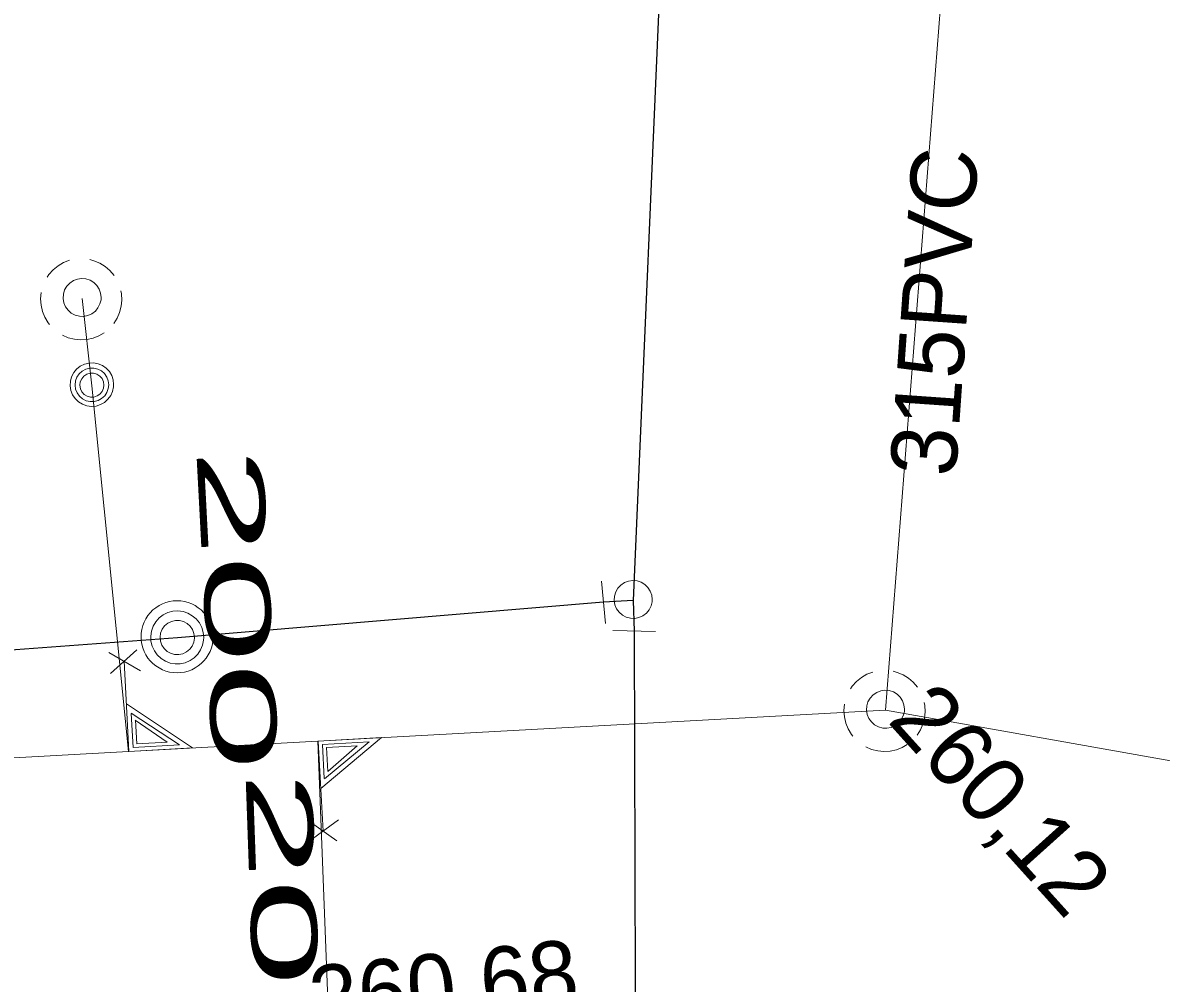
# Model space of a CAD drawing. Extents: x -732074 to -731966, y -1048695 to -1047982.
# Drawn here: x -732046.71 to -732032.89, y -1048041.73 to -1048030.06 of the extents above; entities that cross this region are included whole.
import ezdxf

# ---------------------------------------------------------------- set-up
doc = ezdxf.new("R2010")
doc.units = 0
doc.header["$LTSCALE"] = 0.32
doc.layers.add('1', color=7, linetype='Continuous')
for name, color, linetype, lineweight in [('18', 7, 'Continuous', 13), ('20', 7, 'Continuous', 13), ('49', 7, 'Continuous', 13), ('8', 7, 'Continuous', 13)]:
    doc.layers.add(name, color=color, linetype=linetype, lineweight=lineweight)

msp = doc.modelspace()

# ---------------------------------------------------------------- linework, layer by layer
at = {"layer": '18'}
for p, q in [((-732045.664, -1048037.71), (-732045.28, -1048037.934)), ((-732045.326, -1048037.679), (-732045.646, -1048037.966)), ((-732042.897, -1048039.999), (-732043.246, -1048039.749)), ((-732043.235, -1048040.006), (-732042.878, -1048039.742))]:
    msp.add_line(p, q, dxfattribs=at)
for points in [[(-732046.142, -1048032.947), (-732046.213, -1048032.975), (-732046.279, -1048033.014), (-732046.34, -1048033.062), (-732046.391, -1048033.119), (-732046.414, -1048033.153)], [(-732045.6, -1048033.13), (-732045.651, -1048033.072), (-732045.708, -1048033.022), (-732045.774, -1048032.981), (-732045.845, -1048032.952), (-732045.894, -1048032.938)], [(-732046.487, -1048033.339), (-732046.492, -1048033.416), (-732046.487, -1048033.493), (-732046.47, -1048033.568), (-732046.441, -1048033.639), (-732046.401, -1048033.705), (-732046.386, -1048033.727)], [(-732045.605, -1048033.716), (-732045.565, -1048033.651), (-732045.534, -1048033.581), (-732045.514, -1048033.506), (-732045.507, -1048033.43), (-732045.512, -1048033.353), (-732045.517, -1048033.318)], [(-732046.228, -1048033.856), (-732046.159, -1048033.887), (-732046.083, -1048033.906), (-732046.007, -1048033.913), (-732045.931, -1048033.908), (-732045.855, -1048033.891), (-732045.784, -1048033.863), (-732045.723, -1048033.828)], [(-732045.48, -1048037.816), (-732045.42, -1048038.911), (-732044.65, -1048038.868), (-732045.451, -1048038.334)], [(-732036.392, -1048037.947), (-732036.463, -1048037.975), (-732036.529, -1048038.014), (-732036.59, -1048038.062), (-732036.641, -1048038.119), (-732036.664, -1048038.153)], [(-732035.85, -1048038.13), (-732035.901, -1048038.072), (-732035.958, -1048038.022), (-732036.024, -1048037.981), (-732036.095, -1048037.952), (-732036.144, -1048037.938)], [(-732036.737, -1048038.339), (-732036.742, -1048038.416), (-732036.737, -1048038.493), (-732036.72, -1048038.568), (-732036.691, -1048038.639), (-732036.651, -1048038.705), (-732036.636, -1048038.727)], [(-732035.855, -1048038.716), (-732035.815, -1048038.651), (-732035.784, -1048038.581), (-732035.764, -1048038.506), (-732035.757, -1048038.43), (-732035.762, -1048038.353), (-732035.767, -1048038.318)], [(-732045.394, -1048038.449), (-732045.371, -1048038.864), (-732044.807, -1048038.833), (-732045.394, -1048038.448)], [(-732045.342, -1048038.53), (-732045.326, -1048038.82), (-732044.956, -1048038.8), (-732045.344, -1048038.53)], [(-732043.064, -1048039.879), (-732043.124, -1048038.786), (-732042.355, -1048038.744), (-732043.092, -1048039.363)], [(-732043.049, -1048039.241), (-732043.071, -1048038.827), (-732042.506, -1048038.796), (-732043.048, -1048039.243)], [(-732043.006, -1048039.156), (-732043.022, -1048038.864), (-732042.651, -1048038.844), (-732043.007, -1048039.156)], [(-732036.478, -1048038.856), (-732036.409, -1048038.887), (-732036.333, -1048038.906), (-732036.257, -1048038.913), (-732036.181, -1048038.908), (-732036.105, -1048038.891), (-732036.034, -1048038.863), (-732035.973, -1048038.828)]]:
    msp.add_lwpolyline(points, dxfattribs=at)
for points in [[(-732045.757, -1048033.399), (-732045.764, -1048033.347), (-732045.781, -1048033.297), (-732045.809, -1048033.253), (-732045.848, -1048033.216), (-732045.892, -1048033.189), (-732045.943, -1048033.173), (-732045.995, -1048033.168), (-732046.046, -1048033.175), (-732046.095, -1048033.194), (-732046.139, -1048033.224), (-732046.174, -1048033.263), (-732046.201, -1048033.308), (-732046.215, -1048033.359), (-732046.218, -1048033.411), (-732046.21, -1048033.463), (-732046.19, -1048033.511), (-732046.159, -1048033.554), (-732046.12, -1048033.589), (-732046.073, -1048033.613), (-732046.022, -1048033.627), (-732045.97, -1048033.629), (-732045.919, -1048033.619), (-732045.87, -1048033.597), (-732045.828, -1048033.565), (-732045.796, -1048033.525), (-732045.772, -1048033.478), (-732045.759, -1048033.427)], [(-732045.606, -1048034.457), (-732045.612, -1048034.401), (-732045.629, -1048034.348), (-732045.657, -1048034.299), (-732045.696, -1048034.258), (-732045.742, -1048034.226), (-732045.794, -1048034.204), (-732045.849, -1048034.193), (-732045.905, -1048034.195), (-732045.96, -1048034.208), (-732046.011, -1048034.233), (-732046.055, -1048034.268), (-732046.091, -1048034.311), (-732046.116, -1048034.361), (-732046.131, -1048034.416), (-732046.134, -1048034.472), (-732046.125, -1048034.527), (-732046.104, -1048034.58), (-732046.073, -1048034.626), (-732046.032, -1048034.665), (-732045.985, -1048034.695), (-732045.932, -1048034.714), (-732045.876, -1048034.721), (-732045.82, -1048034.717), (-732045.766, -1048034.7), (-732045.717, -1048034.673), (-732045.675, -1048034.635), (-732045.642, -1048034.59), (-732045.619, -1048034.539), (-732045.607, -1048034.484)], [(-732045.665, -1048034.46), (-732045.671, -1048034.411), (-732045.689, -1048034.365), (-732045.717, -1048034.324), (-732045.754, -1048034.291), (-732045.798, -1048034.269), (-732045.846, -1048034.257), (-732045.895, -1048034.257), (-732045.943, -1048034.269), (-732045.987, -1048034.292), (-732046.024, -1048034.325), (-732046.052, -1048034.366), (-732046.069, -1048034.413), (-732046.075, -1048034.462), (-732046.068, -1048034.511), (-732046.05, -1048034.557), (-732046.022, -1048034.597), (-732045.985, -1048034.63), (-732045.941, -1048034.652), (-732045.892, -1048034.664), (-732045.843, -1048034.663), (-732045.795, -1048034.651), (-732045.752, -1048034.627), (-732045.715, -1048034.594), (-732045.687, -1048034.553), (-732045.671, -1048034.506)], [(-732045.724, -1048034.464), (-732045.73, -1048034.422), (-732045.747, -1048034.384), (-732045.775, -1048034.353), (-732045.809, -1048034.33), (-732045.85, -1048034.319), (-732045.892, -1048034.319), (-732045.932, -1048034.331), (-732045.967, -1048034.354), (-732045.994, -1048034.386), (-732046.011, -1048034.424), (-732046.016, -1048034.465), (-732046.01, -1048034.507), (-732045.992, -1048034.544), (-732045.964, -1048034.576), (-732045.928, -1048034.598), (-732045.888, -1048034.609), (-732045.846, -1048034.608), (-732045.806, -1048034.595), (-732045.772, -1048034.572), (-732045.745, -1048034.539), (-732045.729, -1048034.501)], [(-732036.007, -1048038.399), (-732036.014, -1048038.347), (-732036.031, -1048038.297), (-732036.059, -1048038.253), (-732036.098, -1048038.216), (-732036.142, -1048038.189), (-732036.193, -1048038.173), (-732036.245, -1048038.168), (-732036.296, -1048038.175), (-732036.345, -1048038.194), (-732036.389, -1048038.224), (-732036.424, -1048038.263), (-732036.451, -1048038.308), (-732036.465, -1048038.359), (-732036.468, -1048038.411), (-732036.46, -1048038.463), (-732036.44, -1048038.511), (-732036.409, -1048038.554), (-732036.37, -1048038.589), (-732036.323, -1048038.613), (-732036.272, -1048038.627), (-732036.22, -1048038.629), (-732036.169, -1048038.619), (-732036.12, -1048038.597), (-732036.078, -1048038.565), (-732036.046, -1048038.525), (-732036.022, -1048038.478), (-732036.009, -1048038.427)]]:
    msp.add_lwpolyline(points, close=True, dxfattribs=at)
at = {"layer": '20'}
msp.add_lwpolyline([(-732053.775, -1048039.372), (-732045.426, -1048038.914), (-732043.129, -1048038.788), (-732036.239, -1048038.41), (-732035.469, -1048028.56)], dxfattribs=at)
msp.add_lwpolyline([(-732053.775, -1048039.372), (-732045.426, -1048038.914), (-732043.129, -1048038.788), (-732036.239, -1048038.41), (-732035.469, -1048028.56)], dxfattribs=at)
at = {"layer": '49'}
for p, q in [((-732018.23, -1048041.61), (-732036.239, -1048038.41)), ((-732018.23, -1048041.61), (-732036.239, -1048038.41)), ((-732043, -1048042.12), (-732043.129, -1048038.788)), ((-732043, -1048042.12), (-732043.129, -1048038.788))]:
    msp.add_line(p, q, dxfattribs=at)
msp.add_lwpolyline([(-732045.989, -1048033.41), (-732045.87, -1048034.47), (-732045.426, -1048038.914)], dxfattribs=at)
msp.add_lwpolyline([(-732045.989, -1048033.41), (-732045.87, -1048034.47), (-732045.426, -1048038.914)], dxfattribs=at)
at = {"layer": '8'}
for p, q in [((-732039.636, -1048037.358), (-732039.683, -1048036.843)), ((-732039.029, -1048037.457), (-732039.546, -1048037.442))]:
    msp.add_line(p, q, dxfattribs=at)
at = {"layer": '8', "lineweight": 25}
for p, q in [((-732039.66, -1048037.1), (-732044.829, -1048037.53)), ((-732039.3, -1048037.077), (-732039.66, -1048037.1)), ((-732039.3, -1048037.077), (-732039.289, -1048037.45)), ((-732044.829, -1048037.53), (-732053.698, -1048038.188))]:
    msp.add_line(p, q, dxfattribs=at)
for points in [[(-732033.399, -1047999.11), (-732033.26, -1048005.79), (-732035.475, -1048012.689), (-732038.309, -1048021.518), (-732038.774, -1048026.833), (-732038.94, -1048028.735), (-732039.3, -1048037.077)], [(-732039.289, -1048037.45), (-732039.26, -1048047.48), (-732037.5, -1048060.59), (-732034.1, -1048071.04), (-732029.18, -1048078.35)]]:
    msp.add_lwpolyline(points, dxfattribs=at)
at = {"layer": '8'}
for points in [[(-732039.069, -1048037.066), (-732039.075, -1048037.014), (-732039.093, -1048036.964), (-732039.121, -1048036.92), (-732039.159, -1048036.883), (-732039.204, -1048036.856), (-732039.254, -1048036.84), (-732039.306, -1048036.835), (-732039.358, -1048036.842), (-732039.407, -1048036.861), (-732039.451, -1048036.891), (-732039.486, -1048036.93), (-732039.512, -1048036.975), (-732039.527, -1048037.026), (-732039.53, -1048037.078), (-732039.522, -1048037.13), (-732039.501, -1048037.178), (-732039.471, -1048037.221), (-732039.431, -1048037.256), (-732039.385, -1048037.28), (-732039.334, -1048037.294), (-732039.282, -1048037.296), (-732039.23, -1048037.286), (-732039.182, -1048037.264), (-732039.14, -1048037.232), (-732039.107, -1048037.192), (-732039.083, -1048037.145), (-732039.071, -1048037.094)], [(-732044.512, -1048037.527), (-732044.518, -1048037.466), (-732044.536, -1048037.406), (-732044.565, -1048037.351), (-732044.604, -1048037.303), (-732044.651, -1048037.263), (-732044.705, -1048037.233), (-732044.764, -1048037.213), (-732044.826, -1048037.206), (-732044.888, -1048037.21), (-732044.948, -1048037.226), (-732045.003, -1048037.254), (-732045.053, -1048037.291), (-732045.094, -1048037.338), (-732045.126, -1048037.391), (-732045.146, -1048037.45), (-732045.156, -1048037.511), (-732045.153, -1048037.573), (-732045.138, -1048037.633), (-732045.112, -1048037.69), (-732045.076, -1048037.74), (-732045.03, -1048037.783), (-732044.978, -1048037.815), (-732044.92, -1048037.838), (-732044.859, -1048037.848), (-732044.797, -1048037.847), (-732044.736, -1048037.834), (-732044.679, -1048037.809), (-732044.628, -1048037.774), (-732044.584, -1048037.73), (-732044.55, -1048037.678), (-732044.526, -1048037.621), (-732044.514, -1048037.56)], [(-732044.626, -1048037.527), (-732044.632, -1048037.478), (-732044.649, -1048037.431), (-732044.677, -1048037.39), (-732044.715, -1048037.357), (-732044.759, -1048037.333), (-732044.807, -1048037.321), (-732044.857, -1048037.32), (-732044.905, -1048037.332), (-732044.95, -1048037.354), (-732044.988, -1048037.387), (-732045.017, -1048037.427), (-732045.036, -1048037.474), (-732045.043, -1048037.523), (-732045.038, -1048037.573), (-732045.021, -1048037.62), (-732044.994, -1048037.662), (-732044.957, -1048037.696), (-732044.914, -1048037.72), (-732044.866, -1048037.734), (-732044.816, -1048037.735), (-732044.767, -1048037.725), (-732044.722, -1048037.703), (-732044.683, -1048037.671), (-732044.653, -1048037.632), (-732044.634, -1048037.586), (-732044.626, -1048037.536)]]:
    msp.add_lwpolyline(points, close=True, dxfattribs=at)
msp.add_lwpolyline([(-732044.399, -1048037.519), (-732044.401, -1048037.474), (-732044.408, -1048037.429), (-732044.42, -1048037.384), (-732044.436, -1048037.342), (-732044.457, -1048037.301), (-732044.482, -1048037.262), (-732044.511, -1048037.227), (-732044.543, -1048037.194), (-732044.579, -1048037.166), (-732044.617, -1048037.141), (-732044.658, -1048037.12), (-732044.701, -1048037.103), (-732044.745, -1048037.091), (-732044.79, -1048037.084), (-732044.836, -1048037.082), (-732044.882, -1048037.084), (-732044.927, -1048037.091), (-732044.971, -1048037.103), (-732045.014, -1048037.12), (-732045.055, -1048037.141), (-732045.093, -1048037.166), (-732045.129, -1048037.194), (-732045.161, -1048037.227), (-732045.19, -1048037.262), (-732045.215, -1048037.301), (-732045.236, -1048037.342), (-732045.252, -1048037.384), (-732045.264, -1048037.429), (-732045.271, -1048037.474), (-732045.274, -1048037.52), (-732045.271, -1048037.565), (-732045.264, -1048037.61), (-732045.252, -1048037.655), (-732045.236, -1048037.697), (-732045.215, -1048037.738), (-732045.19, -1048037.777), (-732045.161, -1048037.812), (-732045.129, -1048037.845), (-732045.093, -1048037.873), (-732045.055, -1048037.898), (-732045.014, -1048037.919), (-732044.971, -1048037.936), (-732044.927, -1048037.947), (-732044.882, -1048037.955), (-732044.836, -1048037.957), (-732044.79, -1048037.955), (-732044.745, -1048037.947), (-732044.701, -1048037.936), (-732044.658, -1048037.919), (-732044.617, -1048037.898), (-732044.579, -1048037.873), (-732044.543, -1048037.845), (-732044.511, -1048037.812), (-732044.482, -1048037.777), (-732044.457, -1048037.738), (-732044.436, -1048037.697), (-732044.42, -1048037.655), (-732044.408, -1048037.61), (-732044.401, -1048037.565), (-732044.399, -1048037.52)], dxfattribs=at)

# ---------------------------------------------------------------- texts
at = {"layer": '1'}
for s, rotation, p in [('315PVC', 86, (-732035.387, -1048035.587)), ('260,12', 312, (-732036.227, -1048038.542)), ('260,68', 6, (-732043.188, -1048042.326))]:
    msp.add_text(s, height=0.8, rotation=rotation, dxfattribs=at).set_placement(p)
at = {"layer": '1', "width": 2.2}
for rotation, p in [(273, (-732044.604, -1048035.241)), (272, (-732044.006, -1048039.162))]:
    msp.add_text('200 ', height=0.8, rotation=rotation, dxfattribs=at).set_placement(p)

doc.saveas('drawing.dxf')
